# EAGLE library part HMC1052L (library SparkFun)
HMC1052L Dual axis magnetic sensor. Used for compass and magnetometer applications. Schematic and footprint are not tested and probably need fixing. Spark Fun Electronics SKU : IC-HMC1052L
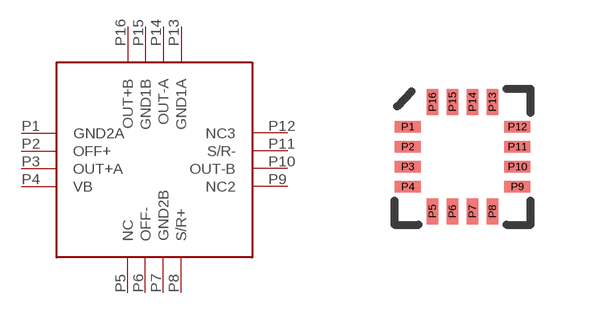
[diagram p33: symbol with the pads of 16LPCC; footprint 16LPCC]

Designator prefix -

## HMC1052L  [16LPCC]
P1  GND2A
P2  OFF+
P3  OUT+A
P4  VB
P5  NC
P6  OFF-
P7  GND2B
P8  S/R+
P9  NC2
P10  OUT-B
P11  S/R-
P12  NC3
P13  GND1A
P14  OUT-A
P15  GND1B
P16  OUT+B

## Footprint 16LPCC (pad centres in mm)
smd 0.65 x 0.28: P1 0.13,2.25; P2 0.13,1.75; P3 0.13,1.25; P4 0.13,0.75; P9 2.87,0.75; P10 2.87,1.25; P11 2.87,1.75; P12 2.87,2.25
smd 0.28 x 0.65: P5 0.75,0.13; P6 1.25,0.13; P7 1.75,0.13; P8 2.25,0.13; P13 2.25,2.87; P14 1.75,2.87; P15 1.25,2.87; P16 0.75,2.87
